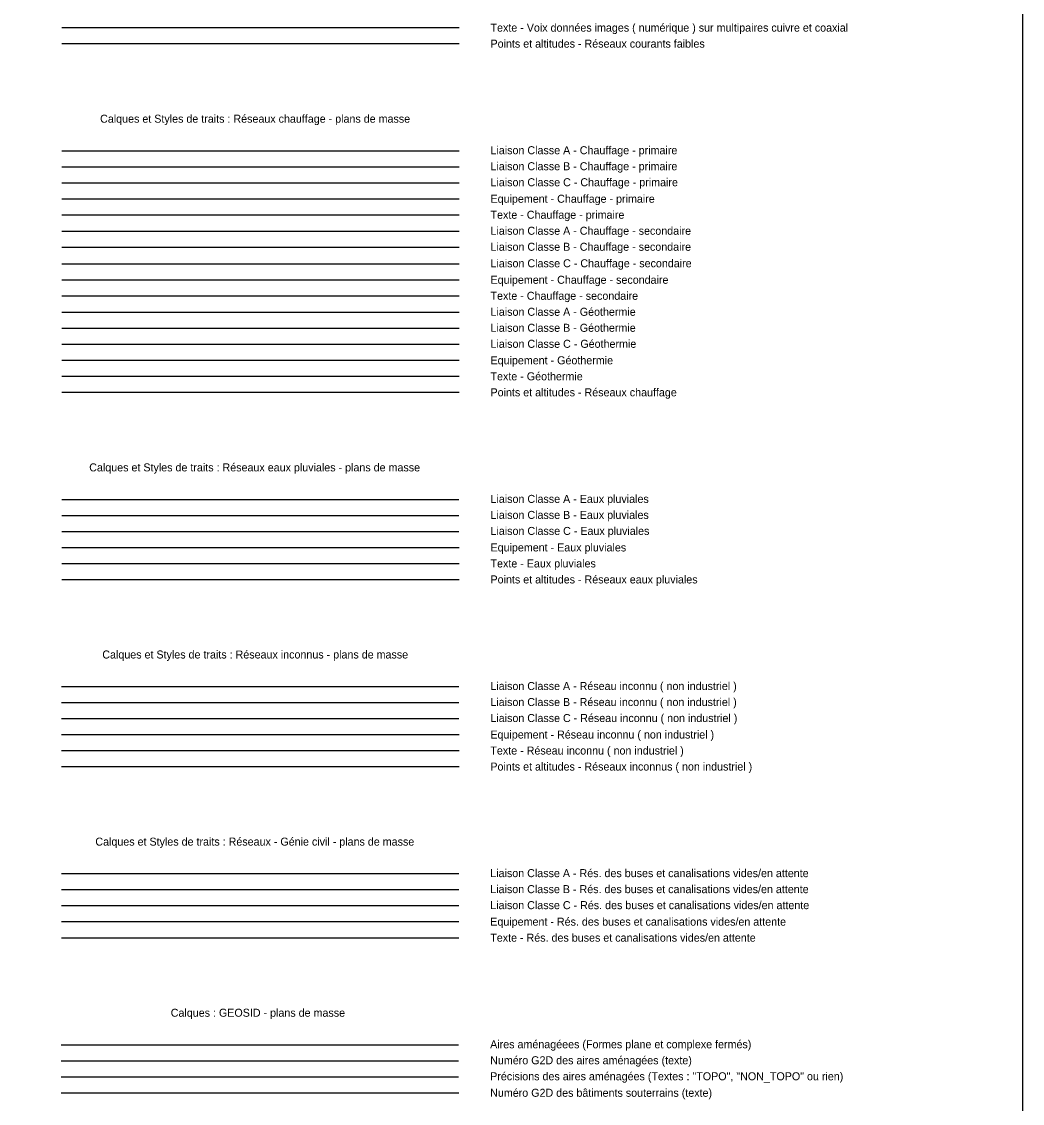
# Model space of a CAD drawing. Extents: x 703432 to 707394, y 7057985 to 7059523.
# Drawn here: x 707262 to 707324.5, y 7058534.5 to 7058602.1 of the extents above; entities that cross this region are included whole.
import ezdxf

# ---------------------------------------------------------------- set-up
doc = ezdxf.new("R2010")
doc.units = 0
for name, color, linetype in [('DH_CADRE -CARTOUCHE', 7, 'Continuous'), ('GEOSID_AIRE_AMENAGEE_NUMERO', 7, 'Continuous'), ('GEOSID_AIRE_AMENAGEE_POLYGONE', 7, 'Continuous'), ('GEOSID_AIRE_AMENAGEE_PRECISION', 7, 'Continuous'), ('GEOSID_BATI_SOUTERRAIN_NUMERO', 7, 'Continuous'), ('R_CF_ALT_POINT', 7, 'Continuous'), ('R_CF_VDI_TEXTE', 7, 'Continuous'), ('R_CH_ALT_POINT', 7, 'Continuous'), ('R_CH_GEOTHERMIE_CANALISATION_CL_A', 7, 'Continuous'), ('R_CH_GEOTHERMIE_CANALISATION_CL_B', 7, 'Continuous'), ('R_CH_GEOTHERMIE_CANALISATION_CL_C', 7, 'Continuous'), ('R_CH_GEOTHERMIE_EQUIP', 7, 'Continuous'), ('R_CH_GEOTHERMIE_TEXTE', 7, 'Continuous'), ('R_CH_PRIM_CANALISATION_CL_A', 7, 'Continuous'), ('R_CH_PRIM_CANALISATION_CL_B', 7, 'Continuous'), ('R_CH_PRIM_CANALISATION_CL_C', 7, 'Continuous'), ('R_CH_PRIM_EQUIP', 7, 'Continuous'), ('R_CH_PRIM_TEXTE', 7, 'Continuous'), ('R_CH_SECOND_CANALISATION_CL_A', 7, 'Continuous'), ('R_CH_SECOND_CANALISATION_CL_B', 7, 'Continuous'), ('R_CH_SECOND_CANALISATION_CL_C', 7, 'Continuous'), ('R_CH_SECOND_EQUIP', 7, 'Continuous'), ('R_CH_SECOND_TEXTE', 7, 'Continuous'), ('R_GC_BUSES_CANA_CL_A', 7, 'Continuous'), ('R_GC_BUSES_CANA_CL_B', 7, 'Continuous'), ('R_GC_BUSES_CANA_CL_C', 7, 'Continuous'), ('R_GC_BUSES_CANA_EQUIP', 7, 'Continuous'), ('R_GC_BUSES_CANA_TEXTE', 7, 'Continuous'), ('R_INCONNU_ALT_POINT', 7, 'Continuous'), ('R_INCONNU_CANALISATION_CL_A', 7, 'Continuous'), ('R_INCONNU_CANALISATION_CL_B', 7, 'Continuous'), ('R_INCONNU_CANALISATION_CL_C', 7, 'Continuous'), ('R_INCONNU_EQUIP', 7, 'Continuous'), ('R_INCONNU_TEXTE', 7, 'Continuous'), ('R_PLU_ALT_POINT', 7, 'Continuous'), ('R_PLU_CANALISATION_CL_A', 7, 'Continuous'), ('R_PLU_CANALISATION_CL_B', 7, 'Continuous'), ('R_PLU_CANALISATION_CL_C', 7, 'Continuous'), ('R_PLU_EQUIP', 7, 'Continuous'), ('R_PLU_TEXTE', 7, 'Continuous')]:
    doc.layers.add(name, color=color, linetype=linetype)

msp = doc.modelspace()

# ---------------------------------------------------------------- linework, layer by layer
at = {"layer": 'DH_CADRE -CARTOUCHE'}
msp.add_lwpolyline([(707199.469, 7058644.551), (707324.469, 7058644.551), (707324.469, 7058419.551), (707199.469, 7058419.551)], close=True, dxfattribs=at)
at = {"layer": 'GEOSID_AIRE_AMENAGEE_NUMERO'}
msp.add_line((707264.447, 7058537.159), (707289.262, 7058537.159), dxfattribs=at)
at = {"layer": 'GEOSID_AIRE_AMENAGEE_POLYGONE'}
msp.add_line((707264.447, 7058538.159), (707289.262, 7058538.159), dxfattribs=at)
at = {"layer": 'GEOSID_AIRE_AMENAGEE_PRECISION'}
msp.add_line((707264.447, 7058536.159), (707289.262, 7058536.159), dxfattribs=at)
at = {"layer": 'GEOSID_BATI_SOUTERRAIN_NUMERO'}
msp.add_line((707264.447, 7058535.159), (707289.276, 7058535.159), dxfattribs=at)
at = {"layer": 'R_CF_ALT_POINT'}
msp.add_line((707264.469, 7058600.701), (707289.298, 7058600.701), dxfattribs=at)
at = {"layer": 'R_CF_VDI_TEXTE'}
msp.add_line((707264.469, 7058601.701), (707289.298, 7058601.701), dxfattribs=at)
at = {"layer": 'R_CH_ALT_POINT'}
msp.add_line((707264.469, 7058578.918), (707289.298, 7058578.918), dxfattribs=at)
at = {"layer": 'R_CH_GEOTHERMIE_CANALISATION_CL_A'}
msp.add_line((707264.469, 7058583.918), (707289.289, 7058583.918), dxfattribs=at)
at = {"layer": 'R_CH_GEOTHERMIE_CANALISATION_CL_B'}
msp.add_line((707264.469, 7058582.918), (707289.289, 7058582.918), dxfattribs=at)
at = {"layer": 'R_CH_GEOTHERMIE_CANALISATION_CL_C'}
msp.add_line((707264.469, 7058581.918), (707289.289, 7058581.918), dxfattribs=at)
at = {"layer": 'R_CH_GEOTHERMIE_EQUIP'}
msp.add_line((707264.469, 7058580.918), (707289.298, 7058580.918), dxfattribs=at)
at = {"layer": 'R_CH_GEOTHERMIE_TEXTE'}
msp.add_line((707264.469, 7058579.918), (707289.298, 7058579.918), dxfattribs=at)
at = {"layer": 'R_CH_PRIM_CANALISATION_CL_A'}
msp.add_line((707264.469, 7058594.011), (707289.289, 7058594.011), dxfattribs=at)
at = {"layer": 'R_CH_PRIM_CANALISATION_CL_B'}
msp.add_line((707264.469, 7058593.011), (707289.289, 7058593.011), dxfattribs=at)
at = {"layer": 'R_CH_PRIM_CANALISATION_CL_C'}
msp.add_line((707264.469, 7058592.011), (707289.289, 7058592.011), dxfattribs=at)
at = {"layer": 'R_CH_PRIM_EQUIP'}
msp.add_line((707264.469, 7058591.011), (707289.298, 7058591.011), dxfattribs=at)
at = {"layer": 'R_CH_PRIM_TEXTE'}
msp.add_line((707264.469, 7058590.011), (707289.298, 7058590.011), dxfattribs=at)
at = {"layer": 'R_CH_SECOND_CANALISATION_CL_A'}
msp.add_line((707264.469, 7058588.98), (707289.289, 7058588.98), dxfattribs=at)
at = {"layer": 'R_CH_SECOND_CANALISATION_CL_B'}
msp.add_line((707264.469, 7058587.98), (707289.289, 7058587.98), dxfattribs=at)
at = {"layer": 'R_CH_SECOND_CANALISATION_CL_C'}
msp.add_line((707264.469, 7058586.949), (707289.289, 7058586.949), dxfattribs=at)
at = {"layer": 'R_CH_SECOND_EQUIP'}
msp.add_line((707264.469, 7058585.949), (707289.298, 7058585.949), dxfattribs=at)
at = {"layer": 'R_CH_SECOND_TEXTE'}
msp.add_line((707264.469, 7058584.949), (707289.298, 7058584.949), dxfattribs=at)
at = {"layer": 'R_GC_BUSES_CANA_CL_A'}
msp.add_line((707264.454, 7058548.849), (707289.269, 7058548.849), dxfattribs=at)
at = {"layer": 'R_GC_BUSES_CANA_CL_B'}
msp.add_line((707264.454, 7058547.849), (707289.269, 7058547.849), dxfattribs=at)
at = {"layer": 'R_GC_BUSES_CANA_CL_C'}
msp.add_line((707264.454, 7058546.849), (707289.269, 7058546.849), dxfattribs=at)
at = {"layer": 'R_GC_BUSES_CANA_EQUIP'}
msp.add_line((707264.454, 7058545.849), (707289.284, 7058545.849), dxfattribs=at)
at = {"layer": 'R_GC_BUSES_CANA_TEXTE'}
msp.add_line((707264.454, 7058544.849), (707289.284, 7058544.849), dxfattribs=at)
at = {"layer": 'R_INCONNU_ALT_POINT'}
msp.add_line((707264.462, 7058555.539), (707289.291, 7058555.539), dxfattribs=at)
at = {"layer": 'R_INCONNU_CANALISATION_CL_A'}
msp.add_line((707264.462, 7058560.539), (707289.276, 7058560.539), dxfattribs=at)
at = {"layer": 'R_INCONNU_CANALISATION_CL_B'}
msp.add_line((707264.462, 7058559.539), (707289.276, 7058559.539), dxfattribs=at)
at = {"layer": 'R_INCONNU_CANALISATION_CL_C'}
msp.add_line((707264.462, 7058558.539), (707289.276, 7058558.539), dxfattribs=at)
at = {"layer": 'R_INCONNU_EQUIP'}
msp.add_line((707264.462, 7058557.539), (707289.291, 7058557.539), dxfattribs=at)
at = {"layer": 'R_INCONNU_TEXTE'}
msp.add_line((707264.462, 7058556.539), (707289.291, 7058556.539), dxfattribs=at)
at = {"layer": 'R_PLU_ALT_POINT'}
msp.add_line((707264.469, 7058567.228), (707289.298, 7058567.228), dxfattribs=at)
at = {"layer": 'R_PLU_CANALISATION_CL_A'}
msp.add_line((707264.469, 7058572.228), (707289.269, 7058572.228), dxfattribs=at)
at = {"layer": 'R_PLU_CANALISATION_CL_B'}
msp.add_line((707264.469, 7058571.228), (707289.269, 7058571.228), dxfattribs=at)
at = {"layer": 'R_PLU_CANALISATION_CL_C'}
msp.add_line((707264.469, 7058570.228), (707289.269, 7058570.228), dxfattribs=at)
at = {"layer": 'R_PLU_EQUIP'}
msp.add_line((707264.469, 7058569.228), (707289.298, 7058569.228), dxfattribs=at)
at = {"layer": 'R_PLU_TEXTE'}
msp.add_line((707264.469, 7058568.228), (707289.298, 7058568.228), dxfattribs=at)

# ---------------------------------------------------------------- texts
at = {"layer": 'DH_CADRE -CARTOUCHE'}
for s, p in [(' Calques et Styles de traits : Réseaux chauffage - plans de masse', (707266.684, 7058595.761)), (' Calques et Styles de traits : Réseaux eaux pluviales - plans de masse', (707266.004, 7058573.978)), (' Calques et Styles de traits : Réseaux inconnus - plans de masse', (707266.82, 7058562.289)), (' Calques et Styles de traits : Réseaux - Génie civil - plans de masse', (707266.386, 7058550.599)), (' Calques : GEOSID - plans de masse', (707271.095, 7058539.909))]:
    msp.add_text(s, height=0.5, dxfattribs=at).set_placement(p)
at = {"layer": 'GEOSID_AIRE_AMENAGEE_NUMERO'}
msp.add_text('Numéro G2D des aires aménagées (texte)', height=0.5, dxfattribs=at).set_placement((707291.23, 7058536.94))
at = {"layer": 'GEOSID_AIRE_AMENAGEE_POLYGONE'}
msp.add_text('Aires aménagéees (Formes plane et complexe fermés)', height=0.5, dxfattribs=at).set_placement((707291.23, 7058537.94))
at = {"layer": 'GEOSID_AIRE_AMENAGEE_PRECISION'}
msp.add_text('Précisions des aires aménagées (Textes : "TOPO", "NON_TOPO" ou rien)', height=0.5, dxfattribs=at).set_placement((707291.23, 7058535.94))
at = {"layer": 'GEOSID_BATI_SOUTERRAIN_NUMERO'}
msp.add_text('Numéro G2D des bâtiments souterrains (texte)', height=0.5, dxfattribs=at).set_placement((707291.23, 7058534.909))
at = {"layer": 'R_CF_ALT_POINT'}
msp.add_text('Points et altitudes - Réseaux courants faibles', height=0.5, dxfattribs=at).set_placement((707291.252, 7058600.451))
at = {"layer": 'R_CF_VDI_TEXTE'}
msp.add_text('Texte - Voix données images ( numérique ) sur multipaires cuivre et coaxial', height=0.5, dxfattribs=at).set_placement((707291.252, 7058601.451))
at = {"layer": 'R_CH_ALT_POINT'}
msp.add_text('Points et altitudes - Réseaux chauffage', height=0.5, dxfattribs=at).set_placement((707291.252, 7058578.668))
at = {"layer": 'R_CH_GEOTHERMIE_CANALISATION_CL_A'}
msp.add_text('Liaison Classe A - Géothermie', height=0.5, dxfattribs=at).set_placement((707291.252, 7058583.699))
at = {"layer": 'R_CH_GEOTHERMIE_CANALISATION_CL_B'}
msp.add_text('Liaison Classe B - Géothermie', height=0.5, dxfattribs=at).set_placement((707291.252, 7058582.699))
at = {"layer": 'R_CH_GEOTHERMIE_CANALISATION_CL_C'}
msp.add_text('Liaison Classe C - Géothermie', height=0.5, dxfattribs=at).set_placement((707291.252, 7058581.699))
at = {"layer": 'R_CH_GEOTHERMIE_EQUIP'}
msp.add_text('Equipement - Géothermie', height=0.5, dxfattribs=at).set_placement((707291.252, 7058580.668))
at = {"layer": 'R_CH_GEOTHERMIE_TEXTE'}
msp.add_text('Texte - Géothermie', height=0.5, dxfattribs=at).set_placement((707291.252, 7058579.668))
at = {"layer": 'R_CH_PRIM_CANALISATION_CL_A'}
msp.add_text('Liaison Classe A - Chauffage - primaire', height=0.5, dxfattribs=at).set_placement((707291.252, 7058593.792))
at = {"layer": 'R_CH_PRIM_CANALISATION_CL_B'}
msp.add_text('Liaison Classe B - Chauffage - primaire', height=0.5, dxfattribs=at).set_placement((707291.252, 7058592.792))
at = {"layer": 'R_CH_PRIM_CANALISATION_CL_C'}
msp.add_text('Liaison Classe C - Chauffage - primaire', height=0.5, dxfattribs=at).set_placement((707291.252, 7058591.792))
at = {"layer": 'R_CH_PRIM_EQUIP'}
msp.add_text('Equipement - Chauffage - primaire', height=0.5, dxfattribs=at).set_placement((707291.252, 7058590.761))
at = {"layer": 'R_CH_PRIM_TEXTE'}
msp.add_text('Texte - Chauffage - primaire', height=0.5, dxfattribs=at).set_placement((707291.252, 7058589.761))
at = {"layer": 'R_CH_SECOND_CANALISATION_CL_A'}
msp.add_text('Liaison Classe A - Chauffage - secondaire ', height=0.5, dxfattribs=at).set_placement((707291.252, 7058588.761))
at = {"layer": 'R_CH_SECOND_CANALISATION_CL_B'}
msp.add_text('Liaison Classe B - Chauffage - secondaire ', height=0.5, dxfattribs=at).set_placement((707291.252, 7058587.761))
at = {"layer": 'R_CH_SECOND_CANALISATION_CL_C'}
msp.add_text('Liaison Classe C - Chauffage - secondaire ', height=0.5, dxfattribs=at).set_placement((707291.252, 7058586.73))
at = {"layer": 'R_CH_SECOND_EQUIP'}
msp.add_text('Equipement - Chauffage - secondaire ', height=0.5, dxfattribs=at).set_placement((707291.252, 7058585.699))
at = {"layer": 'R_CH_SECOND_TEXTE'}
msp.add_text('Texte - Chauffage - secondaire ', height=0.5, dxfattribs=at).set_placement((707291.252, 7058584.699))
at = {"layer": 'R_GC_BUSES_CANA_CL_A'}
msp.add_text('Liaison Classe A - Rés. des buses et canalisations vides/en attente', height=0.5, dxfattribs=at).set_placement((707291.237, 7058548.63))
at = {"layer": 'R_GC_BUSES_CANA_CL_B'}
msp.add_text('Liaison Classe B - Rés. des buses et canalisations vides/en attente', height=0.5, dxfattribs=at).set_placement((707291.237, 7058547.63))
at = {"layer": 'R_GC_BUSES_CANA_CL_C'}
msp.add_text('Liaison Classe C - Rés. des buses et canalisations vides/en attente', height=0.5, dxfattribs=at).set_placement((707291.237, 7058546.63))
at = {"layer": 'R_GC_BUSES_CANA_EQUIP'}
msp.add_text('Equipement - Rés. des buses et canalisations vides/en attente', height=0.5, dxfattribs=at).set_placement((707291.237, 7058545.599))
at = {"layer": 'R_GC_BUSES_CANA_TEXTE'}
msp.add_text('Texte - Rés. des buses et canalisations vides/en attente', height=0.5, dxfattribs=at).set_placement((707291.237, 7058544.599))
at = {"layer": 'R_INCONNU_ALT_POINT'}
msp.add_text('Points et altitudes - Réseaux inconnus ( non industriel )', height=0.5, dxfattribs=at).set_placement((707291.244, 7058555.289))
at = {"layer": 'R_INCONNU_CANALISATION_CL_A'}
msp.add_text('Liaison Classe A - Réseau inconnu ( non industriel )', height=0.5, dxfattribs=at).set_placement((707291.244, 7058560.32))
at = {"layer": 'R_INCONNU_CANALISATION_CL_B'}
msp.add_text('Liaison Classe B - Réseau inconnu ( non industriel )', height=0.5, dxfattribs=at).set_placement((707291.244, 7058559.32))
at = {"layer": 'R_INCONNU_CANALISATION_CL_C'}
msp.add_text('Liaison Classe C - Réseau inconnu ( non industriel )', height=0.5, dxfattribs=at).set_placement((707291.244, 7058558.32))
at = {"layer": 'R_INCONNU_EQUIP'}
msp.add_text('Equipement - Réseau inconnu ( non industriel )', height=0.5, dxfattribs=at).set_placement((707291.244, 7058557.289))
at = {"layer": 'R_INCONNU_TEXTE'}
msp.add_text('Texte - Réseau inconnu ( non industriel )', height=0.5, dxfattribs=at).set_placement((707291.244, 7058556.289))
at = {"layer": 'R_PLU_ALT_POINT'}
msp.add_text('Points et altitudes - Réseaux eaux pluviales', height=0.5, dxfattribs=at).set_placement((707291.252, 7058566.978))
at = {"layer": 'R_PLU_CANALISATION_CL_A'}
msp.add_text('Liaison Classe A - Eaux pluviales', height=0.5, dxfattribs=at).set_placement((707291.252, 7058572.009))
at = {"layer": 'R_PLU_CANALISATION_CL_B'}
msp.add_text('Liaison Classe B - Eaux pluviales', height=0.5, dxfattribs=at).set_placement((707291.252, 7058571.009))
at = {"layer": 'R_PLU_CANALISATION_CL_C'}
msp.add_text('Liaison Classe C - Eaux pluviales', height=0.5, dxfattribs=at).set_placement((707291.252, 7058570.009))
at = {"layer": 'R_PLU_EQUIP'}
msp.add_text('Equipement - Eaux pluviales', height=0.5, dxfattribs=at).set_placement((707291.252, 7058568.978))
at = {"layer": 'R_PLU_TEXTE'}
msp.add_text('Texte - Eaux pluviales', height=0.5, dxfattribs=at).set_placement((707291.252, 7058567.978))

doc.saveas('drawing.dxf')
